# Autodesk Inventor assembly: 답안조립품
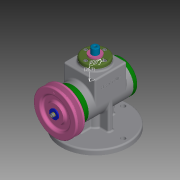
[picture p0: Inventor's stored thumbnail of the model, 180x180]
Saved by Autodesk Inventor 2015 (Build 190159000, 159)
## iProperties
Created: 2020-09
Part Number: 답안조립품
Document SubType Name: Assembly
Designer: LINEART-A501-2
Mass: 2032.85 g
Surface Area: 1710.74 cm^2
Volume: 597.928 cm^3
Density: 3.39983 g/cm^3
Author: LINEART-A501-2
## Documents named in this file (18)
- C:\Users\LINEART-A501-2\Desktop\600906V1028\답안조립품.iam
- C:\Users\LINEART-A501-2\Desktop\600906V1028\본체.ipt
- C:\Users\LINEART-A501-2\Desktop\600906V1028\뒤커버.ipt
- C:\Users\LINEART-A501-2\Desktop\600906V1028\베어링 6203.ipt
- C:\Users\LINEART-A501-2\Desktop\600906V1028\앞커버.ipt
- C:\Users\LINEART-A501-2\Desktop\600906V1028\편심축.ipt
- C:\Users\LINEART-A501-2\Desktop\600906V1028\오일 실 17 30 5.ipt
- C:\Users\LINEART-A501-2\Desktop\600906V1028\가변스프링.ipt
- C:\Users\LINEART-A501-2\Desktop\600906V1028\가이드부시.ipt
- C:\Users\LINEART-A501-2\Desktop\600906V1028\멈춤링.ipt
- C:\Users\LINEART-A501-2\Desktop\600906V1028\상부커버.ipt
- C:\Users\LINEART-A501-2\Desktop\600906V1028\스프링조립용 와셔.ipt
- C:\Users\LINEART-A501-2\Desktop\600906V1028\슬라이더.ipt
- C:\Users\LINEART-A501-2\Desktop\600906V1028\스프링와셔.ipt
- C:\Users\LINEART-A501-2\Desktop\600906V1028\키 4x4x12.ipt
- C:\Users\LINEART-A501-2\Desktop\600906V1028\V-벨트풀리.ipt
- C:\Users\LINEART-A501-2\Desktop\600906V1028\평와셔.ipt
- C:\Users\LINEART-A501-2\Desktop\600906V1028\볼트 M4.ipt
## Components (3 placed, 3 different names)
1. 가변스프링:1
2. 가이드부시:1
3. V-벨트풀리:1 — 각도:2
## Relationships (1: Angle 1)
- 각도:2 [Angle]: V-벨트풀리:1
